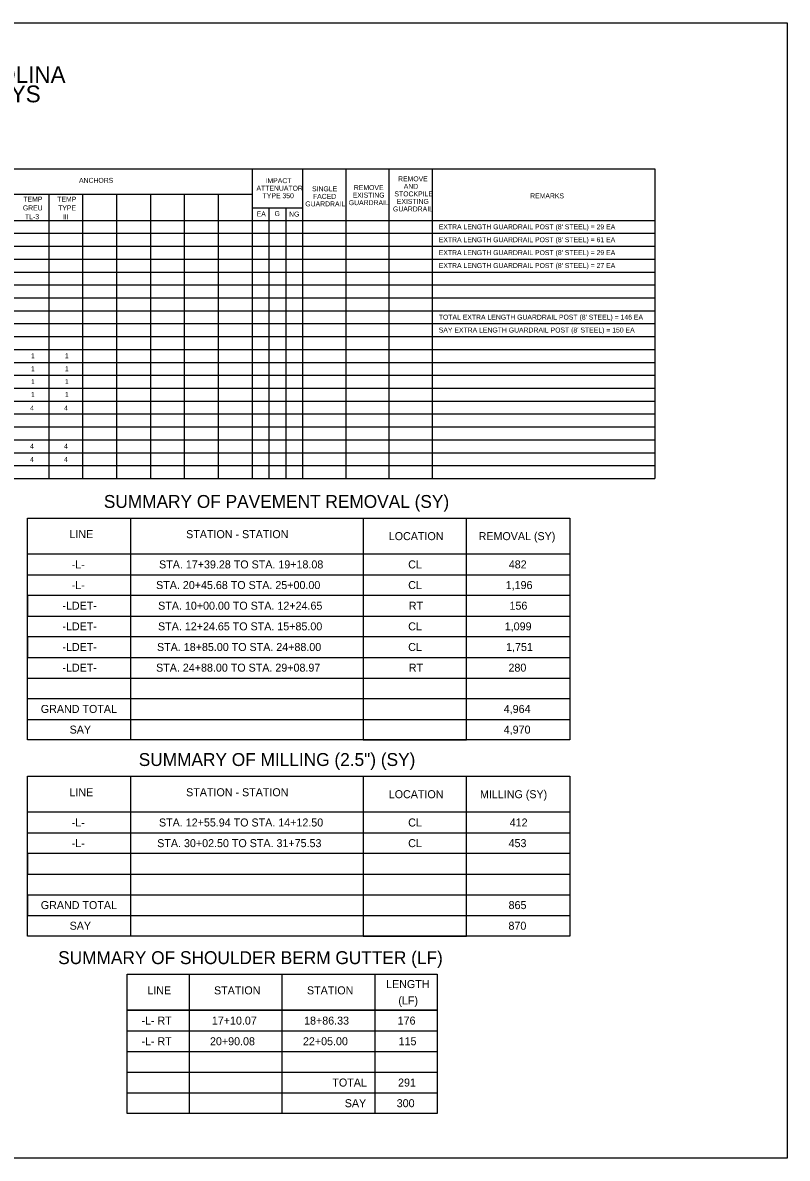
# Model space of a CAD drawing. Extents: x 649560 to 652923, y 1843307 to 1844407.
# Drawn here: x 652182 to 652923, y 1843307 to 1844407 of the extents above; entities that cross this region are included whole.
import ezdxf

# ---------------------------------------------------------------- set-up
doc = ezdxf.new("R2010")
doc.units = 0
doc.layers.add('Default', color=7, linetype='Continuous')
doc.layers.add('P_RDY_Edge_of_Travel', color=7, linetype='Continuous')

msp = doc.modelspace()

# ---------------------------------------------------------------- linework, layer by layer
at = {"layer": 'Default'}
msp.add_lwpolyline([(651222.5, 1844407.2), (652922.5, 1844407.2), (652922.5, 1843307.2), (651222.5, 1843307.2)], close=True, dxfattribs=at)
at = {"layer": 'P_RDY_Edge_of_Travel'}
for p, q in [((651294.4, 1844265.7), (652794.4, 1844265.7)), ((652404.3, 1844265.7), (652404.3, 1843965.7)), ((652453.2, 1844265.7), (652453.2, 1843965.7)), ((652495, 1844265.7), (652495, 1843965.7)), ((652536.8, 1844265.7), (652536.8, 1843965.7)), ((652578.6, 1844265.7), (652578.6, 1843965.7)), ((652794.4, 1844265.7), (652794.4, 1843965.7)), ((652404.3, 1844240.7), (651927.2, 1844240.7)), ((652207.5, 1844240.7), (652207.5, 1843965.7)), ((652240.3, 1844240.7), (652240.3, 1843965.7)), ((652273.1, 1844240.7), (652273.1, 1843965.7)), ((652305.9, 1844240.7), (652305.9, 1843965.7)), ((652338.7, 1844240.7), (652338.7, 1843965.7)), ((652371.5, 1844240.7), (652371.5, 1843965.7)), ((652404.3, 1844228), (652452.9, 1844228)), ((652420.6, 1844228), (652420.7, 1843965.7)), ((652436.9, 1844228), (652437.1, 1843965.7)), ((651294.4, 1844215.7), (652794.4, 1844215.7)), ((651294.4, 1844203.2), (652794.4, 1844203.2)), ((651294.4, 1844190.7), (652794.4, 1844190.7)), ((651294.4, 1844178.2), (652794.4, 1844178.2)), ((651294.4, 1844165.7), (652794.4, 1844165.7)), ((651294.4, 1844153.2), (652794.4, 1844153.2)), ((651294.4, 1844140.7), (652794.4, 1844140.7)), ((651294.4, 1844128.2), (652794.4, 1844128.2)), ((651294.4, 1844115.7), (652794.4, 1844115.7)), ((651294.4, 1844103.2), (652794.4, 1844103.2)), ((651294.4, 1844090.7), (652794.4, 1844090.7)), ((651294.4, 1844078.2), (652794.4, 1844078.2)), ((651294.4, 1844065.7), (652794.4, 1844065.7)), ((651294.4, 1844053.2), (652794.4, 1844053.2)), ((651294.4, 1844040.7), (652794.4, 1844040.7)), ((651294.4, 1844028.2), (652794.4, 1844028.2)), ((651294.4, 1844015.7), (652794.4, 1844015.7)), ((651294.4, 1844003.2), (652794.4, 1844003.2)), ((651294.4, 1843990.7), (652794.4, 1843990.7)), ((651294.4, 1843978.2), (652794.4, 1843978.2)), ((651294.4, 1843965.7), (652794.4, 1843965.7)), ((652186.9, 1843872.4), (652711.9, 1843872.4)), ((652711.9, 1843872.4), (652711.9, 1843852.4)), ((652186.9, 1843852.4), (652186.9, 1843832.4)), ((652711.9, 1843852.4), (652186.9, 1843852.4)), ((652186.9, 1843832.4), (652711.9, 1843832.4)), ((652711.9, 1843832.4), (652711.9, 1843812.4)), ((652186.9, 1843812.4), (652186.9, 1843792.4)), ((652711.9, 1843812.4), (652186.9, 1843812.4)), ((652186.9, 1843792.4), (652711.9, 1843792.4)), ((652711.9, 1843792.4), (652711.9, 1843772.4)), ((652186.9, 1843772.4), (652711.9, 1843772.4)), ((652711.9, 1843752.4), (652186.9, 1843752.4)), ((652186.9, 1843732.4), (652711.9, 1843732.4)), ((652186.9, 1843622.4), (652711.9, 1843622.4)), ((652711.9, 1843622.4), (652711.9, 1843602.4)), ((652186.9, 1843602.4), (652186.9, 1843582.4)), ((652711.9, 1843602.4), (652186.9, 1843602.4)), ((652186.9, 1843582.4), (652711.9, 1843582.4)), ((652711.9, 1843582.4), (652711.9, 1843562.4)), ((652186.9, 1843562.4), (652186.9, 1843542.4)), ((652186.9, 1843562.4), (652711.9, 1843562.4)), ((652186.9, 1843542.4), (652711.9, 1843542.4)), ((652343.3, 1843485.6), (652343.3, 1843350.6)), ((652433.3, 1843485.6), (652433.3, 1843350.6)), ((652523.3, 1843485.6), (652523.3, 1843350.6)), ((652583.4, 1843465.6), (652583.4, 1843350.6)), ((652283.3, 1843450.6), (652343.3, 1843450.6)), ((652343.3, 1843450.6), (652433.3, 1843450.6)), ((652433.3, 1843450.6), (652523.3, 1843450.6)), ((652523.3, 1843450.6), (652583.4, 1843450.6)), ((652283.3, 1843430.6), (652583.4, 1843430.6)), ((652283.3, 1843410.6), (652583.4, 1843410.6)), ((652283.3, 1843390.6), (652583.4, 1843390.6)), ((652283.3, 1843370.6), (652583.4, 1843370.6))]:
    msp.add_line(p, q, dxfattribs=at)
for points in [[(652186.9, 1843927.4), (652711.9, 1843927.4), (652711.9, 1843712.4), (652186.9, 1843712.4)], [(652186.9, 1843677.4), (652711.9, 1843677.4), (652711.9, 1843522.4), (652186.9, 1843522.4)], [(652283.3, 1843485.6), (652583.4, 1843485.6), (652583.4, 1843350.6), (652283.3, 1843350.6)]]:
    msp.add_lwpolyline(points, close=True, dxfattribs=at)
for points in [[(652286.9, 1843712.4), (652286.9, 1843927.4), (652511.9, 1843927.4), (652511.9, 1843712.4), (652611.9, 1843712.4), (652611.9, 1843927.4), (652711.9, 1843927.4), (652711.9, 1843712.4)], [(652711.9, 1843892.4), (652186.9, 1843892.4)], [(652286.9, 1843522.4), (652286.9, 1843677.4), (652511.9, 1843677.4), (652511.9, 1843522.4), (652611.9, 1843522.4), (652611.9, 1843677.4), (652711.9, 1843677.4), (652711.9, 1843522.4)], [(652711.9, 1843642.4), (652186.9, 1843642.4)], [(652583.4, 1843450.6), (652283.3, 1843450.6)]]:
    msp.add_lwpolyline(points, dxfattribs=at)

# ---------------------------------------------------------------- texts
for s, height, p in [('STATE OF NORTH CAROLINA', 16.25, (651917.1, 1844348.8)), ('DIVISION OF HIGHWAYS', 16.25, (651943.7, 1844330.1)), ('ANCHORS', 4.8, (652236.8, 1844252.1)), ('ATTENUATOR', 4.8, (652408.6, 1844244.5)), ('IMPACT', 4.8, (652417.4, 1844251.8)), ('REMOVE', 4.8, (652502.9, 1844245.1)), ('REMOVE', 4.8, (652545.7, 1844253.6)), ('AND', 4.8, (652551.2, 1844246.3)), ('TEMP', 4.8, (652182.9, 1844233.9)), ('TEMP', 4.8, (652215.7, 1844233.9)), ('TYPE 350', 4.8, (652414.6, 1844237.2)), ('SINGLE', 4.8, (652462.4, 1844243.9)), ('FACED', 4.8, (652463.3, 1844236.6)), ('EXISTING', 4.8, (652501.7, 1844237.8)), ('STOCKPILE', 4.8, (652542.2, 1844239)), ('REMARKS', 4.8, (652673.6, 1844237.1)), ('GREU', 4.8, (652182.4, 1844225.4)), ('TYPE', 4.8, (652216.6, 1844225.4)), ('GUARDRAIL', 4.8, (652455.9, 1844229.3)), ('GUARDRAIL', 4.8, (652498, 1844230.5)), ('GUARDRAIL', 4.8, (652540.8, 1844224.4)), ('EXISTING', 4.8, (652544.5, 1844231.7)), ('TL-3', 4.8, (652184.5, 1844216.9)), ('III', 4.8, (652221.2, 1844216.9)), ('EA', 4.8, (652408.8, 1844219.6)), ('G', 4.8, (652426.1, 1844219.9)), ('NG', 4.8, (652440.2, 1844219.4)), ("EXTRA LENGTH GUARDRAIL POST (8' STEEL) = 29 EA", 4.8, (652585.1, 1844207.1)), ("EXTRA LENGTH GUARDRAIL POST (8' STEEL) = 61 EA", 4.8, (652585.1, 1844194.6)), ("EXTRA LENGTH GUARDRAIL POST (8' STEEL) = 29 EA", 4.8, (652585.1, 1844182.1)), ("EXTRA LENGTH GUARDRAIL POST (8' STEEL) = 27 EA", 4.8, (652585.1, 1844169.6)), ("TOTAL EXTRA LENGTH GUARDRAIL POST (8' STEEL) = 146 EA", 4.8, (652585.1, 1844119.6)), ("SAY EXTRA LENGTH GUARDRAIL POST (8' STEEL) = 150 EA", 4.8, (652585.1, 1844107.1)), ('1', 4.8, (652190.3, 1844082.1)), ('1', 4.8, (652223.1, 1844082.1)), ('1', 4.8, (652190.3, 1844069.6)), ('1', 4.8, (652223.1, 1844069.6)), ('1', 4.8, (652190.3, 1844057.1)), ('1', 4.8, (652223.1, 1844057.1)), ('1', 4.8, (652190.3, 1844044.6)), ('1', 4.8, (652223.1, 1844044.6)), ('4', 4.8, (652189.5, 1844031.6)), ('4', 4.8, (652222.3, 1844031.6)), ('4', 4.8, (652189.4, 1843994.6)), ('4', 4.8, (652222.3, 1843994.6)), ('4', 4.8, (652189.4, 1843981.8)), ('4', 4.8, (652222.3, 1843981.8)), ('SUMMARY OF PAVEMENT REMOVAL (SY)', 12.5, (652260.8, 1843937.2)), ('LINE', 7.75, (652227.5, 1843907.9)), ('STATION - STATION', 7.75, (652340.5, 1843907.9)), ('LOCATION', 7.75, (652536.7, 1843906)), ('REMOVAL (SY)', 7.75, (652623.7, 1843906)), ('-L-', 7.75, (652229.7, 1843878.6)), ('STA. 17+39.28 TO STA. 19+18.08', 7.75, (652314.3, 1843878.6)), ('CL', 7.75, (652555.5, 1843878.6)), ('482', 7.75, (652652.9, 1843878.6)), ('-L-', 7.75, (652229.7, 1843858.6)), ('STA. 20+45.68 TO STA. 25+00.00', 7.75, (652311.4, 1843858.6)), ('CL', 7.75, (652555.5, 1843858.6)), ('1,196', 7.75, (652649.9, 1843858.6)), ('-LDET-', 7.75, (652220.7, 1843838.6)), ('STA. 10+00.00 TO STA. 12+24.65', 7.75, (652313.4, 1843838.6)), ('RT', 7.75, (652556.1, 1843838.6)), ('156', 7.75, (652653.6, 1843838.6)), ('-LDET-', 7.75, (652220.7, 1843818.6)), ('STA. 12+24.65 TO STA. 15+85.00', 7.75, (652313.3, 1843818.6)), ('CL', 7.75, (652555.5, 1843818.6)), ('1,099', 7.75, (652649, 1843818.6)), ('-LDET-', 7.75, (652220.7, 1843798.6)), ('STA. 18+85.00 TO STA. 24+88.00', 7.75, (652312.3, 1843798.6)), ('CL', 7.75, (652555.5, 1843798.6)), ('1,751', 7.75, (652650.3, 1843798.6)), ('-LDET-', 7.75, (652220.7, 1843778.6)), ('STA. 24+88.00 TO STA. 29+08.97', 7.75, (652311.4, 1843778.6)), ('RT', 7.75, (652556.1, 1843778.6)), ('280', 7.75, (652652.6, 1843778.6)), ('GRAND TOTAL', 7.75, (652199.8, 1843738.6)), ('4,964', 7.75, (652648, 1843738.6)), ('SAY', 7.75, (652227.7, 1843718.6)), ('4,970', 7.75, (652648, 1843718.6)), ('SUMMARY OF MILLING (2.5") (SY)', 12.5, (652294.6, 1843687.2)), ('LINE', 7.75, (652227.5, 1843657.9)), ('STATION - STATION', 7.75, (652340.5, 1843657.9)), ('LOCATION', 7.75, (652536.7, 1843656)), ('MILLING (SY)', 7.75, (652625, 1843656)), ('-L-', 7.75, (652229.7, 1843628.6)), ('STA. 12+55.94 TO STA. 14+12.50', 7.75, (652314.2, 1843628.6)), ('CL', 7.75, (652555.5, 1843628.6)), ('412', 7.75, (652653.8, 1843628.6)), ('-L-', 7.75, (652229.7, 1843608.6)), ('STA. 30+02.50 TO STA. 31+75.53', 7.75, (652312.5, 1843608.6)), ('CL', 7.75, (652555.5, 1843608.6)), ('453', 7.75, (652652.7, 1843608.6)), ('GRAND TOTAL', 7.75, (652199.8, 1843548.6)), ('865', 7.75, (652652.7, 1843548.6)), ('SAY', 7.75, (652227.7, 1843528.6)), ('870', 7.75, (652652.6, 1843528.6)), ('SUMMARY OF SHOULDER BERM GUTTER (LF)', 12.5, (652216.6, 1843495.3)), ('LENGTH ', 7.75, (652534.1, 1843472.1)), ('LINE', 7.75, (652302.9, 1843466)), ('STATION', 7.75, (652367.5, 1843466)), ('STATION', 7.75, (652457.5, 1843466)), ('(LF)', 7.75, (652546, 1843456.2)), ('-L- RT', 7.75, (652297.2, 1843436.7)), ('17+10.07', 7.75, (652365.4, 1843436.7)), ('18+86.33', 7.75, (652454.7, 1843436.7)), ('176', 7.75, (652545.3, 1843436.7)), ('-L- RT', 7.75, (652297.2, 1843416.7)), ('20+90.08', 7.75, (652363.6, 1843416.7)), ('22+05.00', 7.75, (652453.6, 1843416.7)), ('115', 7.75, (652546.2, 1843416.7)), ('TOTAL', 7.75, (652482.1, 1843376.7)), ('291', 7.75, (652545.7, 1843376.7)), ('SAY', 7.75, (652494.1, 1843356.7)), ('300', 7.75, (652544.4, 1843356.7))]:
    msp.add_text(s, height=height, dxfattribs=at).set_placement(p)

doc.saveas('drawing.dxf')
